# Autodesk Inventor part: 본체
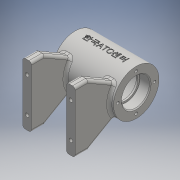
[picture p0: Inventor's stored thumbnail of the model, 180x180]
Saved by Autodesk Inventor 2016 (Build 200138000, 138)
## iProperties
Created: 2018-05
Part Number: 본체
Material: 일반
Document SubType Name: Modeling
Designer: USER
Density: 1 g/cm^3
Appearance: 기본값
Author: USER
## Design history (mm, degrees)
sketch "스케치1"
  geometry: L1 (-38.025, 0)-(38.025, 0); L2 (-35, 26)-(35, 26); L3 (35, 26)-(35, 16); L4 (35, 16)-(23, 16); L5 (23, 16)-(23, 14); L6 (23, 14)-(21, 14); L7 (21, 14)-(21, 21); L8 (21, 21)-(-21, 21); L9 (-21, 21)-(-21, 14); L10 (-21, 14)-(-23, 14); L11 (-23, 14)-(-23, 16); L12 (-23, 16)-(-35, 16); L13 (-35, 16)-(-35, 26); 3 further points
  constraints: 26 end point, 9 perpendicular, 2 horizontal, 2 midpoint, 2 point on line, 1 coincident, 1 vertical, 1 vertical alignment
  dimensions: "d0" = 70 distance of L2.start L2.end; "d1" = 52 diameter of L2 L1; "d2" = 32 diameter of L4 L1; "d3" = 12 distance of L3.end L4.end; "d4" = 28 diameter of L6 L1; "d5" = 2 distance of L5.end L6.end; "d6" = 42 distance of L7.end L8.end; "d7" = 42 diameter of L8 L1; "d8" = 2 distance of L9.end L10.end; "d9" = 32 diameter of L12 L1
revolve "회전1" sketch "스케치1" stored, may be unused: angle "d10" = 90 deg
node "작업 평면1"
sketch "스케치2"
  geometry: L1 (-35, 26)-(-35, -26) reference; L2 (35, 26)-(35, -26) reference; L3 (20, 35)-(20, -35); L4 (35, 0)-(0, 0); L5 (-20, 35)-(-20, -35); L6 (30, 35)-(30, -35); L7 (-30, 35)-(-30, -35); L8 (30, 35)-(20, 35); L9 (30, -35)-(20, -35); L10 (-20, -35)-(-30, -35); L11 (-20, 35)-(-30, 35); 4 further points
  constraints: 18 end point, 5 midpoint, 4 horizontal alignment, 4 vertical, 3 parallel, 2 horizontal, 2 perpendicular, 1 collinear
  dimensions: "d12" = 35 distance of L4.start L4.end (derived); "d13" = 20 distance from line of L4.end L3; "d14" = 40 distance between parallel lines of L5 L3; "d15" = 10 distance between parallel lines of L6 L3; "d16" = 10 distance between parallel lines of L7 L5; "d17" = 70 distance of L6.start L6.end
extrude "돌출1" join sketch "스케치2" distance "d18" = 15; taper "d19" = 0 deg
sketch "스케치3"
  geometry: L1 (0, 15)-(70, 15) reference; L2 (70, 15)-(0, 15) reference; L3 (70, 15)-(52.325, 45.614); L4 (0, 15)-(17.675, 45.614); A1 r 26 centre (35, 65) between (17.675, 45.614) and (52.325, 45.614) reference; 1 further point
  constraints: 4 end point, 2 point on circle
  dimensions: "d21" = 120 deg angle of L1 L3; "d22" = 120 deg angle of L1 L4
extrude "돌출2" join sketch "스케치3" distance "d23" = 10; taper "d24" = 0 deg
sketch "스케치4"
  geometry: 2 further points
  constraints: 1 vertical alignment
  dimensions: "d25" = 21 distance of point (0, 21) point (0, 0)
hole "구멍1" sketch "스케치4" at (0, 21) diameter "d26" = 3.242; stored, may be unused: countersink angle "d30" = 90 deg, drill point angle "d32" = 118 deg; dims "d27" = 8, "d28" = 4, "d29" = 2, "d31" = 10
node "작업 평면2"
sketch "스케치5"
  geometry: C1 r 5 at (0, 0); 1 further point
  constraints: 1 centre point, 1 coincident
  dimensions: "d37" = 10 diameter of C1
extrude "돌출3" join sketch "스케치5" stored distance "d38" = 10; taper "d39" = 0 deg
sketch "스케치6"
  geometry: 1 further point
hole "구멍2" sketch "스케치6" at (0, 0) diameter "d40" = 5.188; stored, may be unused: countersink angle "d44" = 90 deg, drill point angle "d46" = 118 deg; dims "d41" = 20, "d42" = 4, "d43" = 2, "d45" = 20
sketch "스케치7"
  geometry: L1 (30, -35)-(30, 35) reference; 3 further points
  constraints: 1 vertical alignment
  dimensions: "d47" = 20 vertical distance of point (0, 0) point (25, -20); "d48" = 5 distance from line of L1 point (25, -20); "d49" = 40 distance of point (25, 20) point (25, -20)
hole "구멍3" sketch "스케치7" at (25, -20), (25, 20) diameter "d50" = 4.134; stored, may be unused: countersink angle "d54" = 90 deg, drill point angle "d56" = 118 deg; dims "d51" = 8, "d52" = 4, "d53" = 2, "d55" = 10
node "작업 평면4"
sketch "스케치9"
  geometry: L1 (0, 0)-(-29, 0); L2 (0, 0)-(-27.251, -9.919); L3 (-25.199, -15.557)-(-21.72, -14.291); L4 (-25.199, -15.557)-(-27.251, -9.919); L5 (-27.251, -9.919)-(-24.432, -8.893); A1 r 26 centre (0, 0) between (-19.386, 17.325) and (-19.386, -17.325) reference
  constraints: 10 end point, 2 point on circle, 1 equal length, 1 horizontal, 1 point on line
  dimensions: "d59" = 20 deg angle of L2 L1; "d60" = 29 distance of L1.start L1.end; "d61" = 6 distance between parallel lines of L3 L2; "d62" = 5.63816 vertical distance of L3.start L2.end
revolve "회전2" sketch "스케치9" stored, may be unused: angle "d63" = 90 deg
sketch "스케치10"
  geometry: 1 further point
hole "구멍4" sketch "스케치10" at (0, 0) diameter "d64" = 5.188; stored, may be unused: countersink angle "d68" = 90 deg, drill point angle "d70" = 118 deg; dims "d65" = 20, "d66" = 4, "d67" = 2, "d69" = 20
fillet "모깎기1" dims "d71" = 2
fillet "모깎기2" dims "d72" = 0.3
chamfer "모따기1" distance "d73" = 1; stored, may be unused: second distance "d74" = 2, angle "d75" = 45 deg
fillet "모깎기3" dims "d76" = 3
fillet "모깎기4" dims "d77" = 3
fillet "모깎기5" dims "d78" = 3
node "작업 평면5"
sketch "스케치11"
  geometry: 1 further point
node "작업 평면6"
sketch "스케치12"
  geometry: L1 (-35, 26)-(35, 26) reference; L2 (-35, -26)-(-35, 26) reference; 2 further points
  constraints: 1 other
  dimensions: "d82" = 35 distance from line of point (0, 0) L2; "d83" = 26 distance from line of point (0, 0) L1
feature "엠보싱1" sketch "스케치12" dims "d84" = 0.5, "d85" = 0
node "솔리드1"
mirror "대칭1"
pattern_circular "원형 패턴1" dims angle "d34" = 360 deg
mirror "대칭2"
mirror "대칭3"
node "투영된 루프1"
other parameters: "d11" = -65, "d36" = 29, "d58" = 0, "d79" = -47.25, "d80" = 59.5
